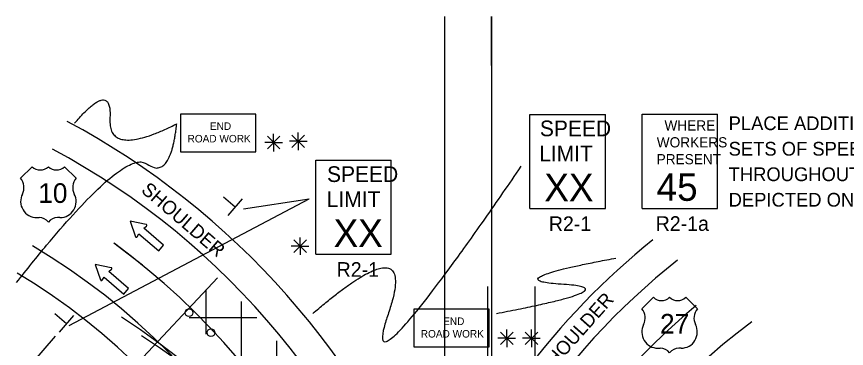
# Model space of a CAD drawing. Extents: x 16284 to 18465, y 5417 to 6974.
# Drawn here: x 16726.3 to 17149.1, y 6805 to 6974.1 of the extents above; entities that cross this region are included whole.
import ezdxf

# ---------------------------------------------------------------- set-up
doc = ezdxf.new("R2010")
doc.units = 0
for name, color, linetype in [('ALI_LEGAL_EX', 7, 'Continuous'), ('Level 3', 7, 'Continuous'), ('MT_SCRATCH_LEVEL_A', 7, 'Continuous'), ('MT_SCRATCH_LEVEL_E', 7, 'Continuous'), ('PAVT_EDGE_EX', 7, 'Continuous'), ('TRAFFIC_SIGNS_PR', 7, 'Continuous'), ('TYPICAL_EX', 7, 'Continuous'), ('TYPICAL_TEXT_DIMEN_PR', 7, 'Continuous')]:
    doc.layers.add(name, color=color, linetype=linetype)

msp = doc.modelspace()

# ---------------------------------------------------------------- linework, layer by layer
at = {"layer": 'ALI_LEGAL_EX'}
for p, q in [((16944.3, 6974.12), (16944.3, 6155.98)), ((16968.3, 6974.12), (16968.3, 6155.98)), ((16966.29, 6836.53), (16966.29, 5997.6)), ((16990.29, 6836.53), (16990.29, 5997.6))]:
    msp.add_line(p, q, dxfattribs=at)
for points in [[(16968.3, 6949.12), (16968.3, 6974.12)], [(16790.41, 6847.41), (16775.85, 6858.63)]]:
    msp.add_lwpolyline(points, dxfattribs=at)
for centre, radius, start, end in [((16561.13, 6564.7), 364, 0, 53.7921), ((17289.13, 6564.7), 340, 129.5666, 180), ((16583.12, 6514.52), 364, 0, 57.2958), ((16593.27, 6505.1), 364, 0, 57.2958)]:
    msp.add_arc(centre, radius, start, end, dxfattribs=at)
at = {"layer": 'Level 3'}
msp.add_line((16753.12, 6816.56), (16875.44, 6881.26), dxfattribs=at)
at = {"layer": 'MT_SCRATCH_LEVEL_A'}
for p, q in [((16822.96, 6812.16), (16822.96, 6834.85)), ((16840.96, 6792.95), (16840.96, 6828.84)), ((16814.28, 6820.72), (16848.67, 6820.72)), ((16858.96, 6769.95), (16858.96, 6808.85))]:
    msp.add_line(p, q, dxfattribs=at)
at = {"layer": 'MT_SCRATCH_LEVEL_E'}
for p, q in [((16792.3, 6868.17), (16784.11, 6869.75)), ((16784.11, 6869.75), (16786.92, 6861.91)), ((16791.11, 6866.22), (16792.51, 6867.36)), ((16801.16, 6857.58), (16791.11, 6866.22)), ((16787.75, 6861.83), (16788.67, 6863.38)), ((16788.67, 6863.38), (16798.72, 6854.74)), ((16798.72, 6854.74), (16801.16, 6857.58)), ((16774.54, 6846.12), (16766.34, 6847.69)), ((16766.34, 6847.69), (16769.15, 6839.86)), ((16773.34, 6844.17), (16774.74, 6845.31)), ((16783.4, 6835.52), (16773.34, 6844.17)), ((16769.98, 6839.78), (16770.91, 6841.33)), ((16770.91, 6841.33), (16780.96, 6832.68)), ((16780.96, 6832.68), (16783.4, 6835.52))]:
    msp.add_line(p, q, dxfattribs=at)
for centre, start, end in [((16792.21, 6867.72), 309.3361, 79.073), ((16787.35, 6862.07), 199.7248, 329.2637), ((16774.44, 6845.66), 309.3361, 79.073), ((16769.59, 6840.02), 199.7248, 329.2637)]:
    msp.add_arc(centre, 0.463, start, end, dxfattribs=at)
at = {"layer": 'PAVT_EDGE_EX'}
for centre, radius, start, end in [((16561.13, 6564.7), 404, 21.0961, 61.7914), ((16561.13, 6564.7), 388, 17.512, 61.7914), ((16561.13, 6564.7), 340, 0, 59.3712), ((17289.13, 6564.7), 380, 128.9165, 157.5011), ((17289.13, 6564.7), 364, 128.3887, 165.0045), ((16561.13, 6564.7), 324, 0, 59.2832), ((17289.13, 6564.7), 316, 126.5777, 180)]:
    msp.add_arc(centre, radius, start, end, dxfattribs=at)
at = {"layer": 'TRAFFIC_SIGNS_PR'}
for p, q in [((16987.86, 6924.25), (17026.26, 6924.25)), ((16987.86, 6876.25), (16987.86, 6924.25)), ((17026.26, 6876.25), (17026.26, 6924.25)), ((17045.06, 6924.34), (17083.46, 6924.34)), ((17045.06, 6876.34), (17045.06, 6924.34)), ((17083.46, 6876.34), (17083.46, 6924.34)), ((16878.7, 6900.93), (16917.1, 6900.93)), ((16878.7, 6852.93), (16878.7, 6900.93)), ((16917.1, 6852.93), (16917.1, 6900.93)), ((16987.86, 6876.25), (17026.26, 6876.25)), ((17045.06, 6876.34), (17083.46, 6876.34)), ((16878.7, 6852.93), (16917.1, 6852.93))]:
    msp.add_line(p, q, dxfattribs=at)
for points in [[(16809.82, 6905.22), (16848.22, 6905.22), (16848.22, 6924.42), (16809.82, 6924.42)], [(16928.61, 6805.76), (16967.01, 6805.76), (16967.01, 6824.96), (16928.61, 6824.96)]]:
    msp.add_lwpolyline(points, close=True, dxfattribs=at)
for centre in [(16814.15, 6823.16), (16825.34, 6812.99)]:
    msp.add_circle(centre, 2, dxfattribs=at)
at = {"layer": 'TYPICAL_EX'}
for p, q in [((16728.37, 6891.7), (16734.26, 6897.6)), ((16756.67, 6891.7), (16750.77, 6897.6)), ((16736.61, 6871.64), (16737.79, 6871.64)), ((16748.42, 6871.64), (16747.24, 6871.64)), ((17044.83, 6825.12), (17050.72, 6831.02)), ((17073.13, 6825.12), (17067.23, 6831.02)), ((17053.08, 6805.06), (17054.25, 6805.06)), ((17064.88, 6805.06), (17063.7, 6805.06))]:
    msp.add_line(p, q, dxfattribs=at)
for centre, radius, start, end in [((16738.39, 6901.89), 5.96, 226.1404, 313.8596), ((16746.64, 6901.89), 5.96, 226.1404, 313.8596), ((16722.78, 6886.98), 7.31, 333.0977, 40.1936), ((16762.25, 6886.98), 7.31, 139.8064, 206.9023), ((16736.63, 6879.89), 8.24, 152.6698, 269.9013), ((16748.41, 6879.89), 8.24, 270.0987, 27.3302), ((16737.81, 6865.74), 5.91, 37.1038, 90.1385), ((16747.23, 6865.74), 5.91, 89.8615, 142.8962), ((17054.85, 6835.31), 5.96, 226.1404, 313.8596), ((17063.11, 6835.31), 5.96, 226.1404, 313.8596), ((17039.24, 6820.4), 7.31, 333.0977, 40.1936), ((17078.72, 6820.4), 7.31, 139.8064, 206.9023), ((17053.09, 6813.31), 8.24, 152.6698, 269.9013), ((17064.87, 6813.31), 8.24, 270.0987, 27.3302), ((17054.27, 6799.16), 5.91, 37.1038, 90.1385), ((17063.69, 6799.16), 5.91, 89.8615, 142.8962)]:
    msp.add_arc(centre, radius, start, end, dxfattribs=at)
at = {"layer": 'TYPICAL_TEXT_DIMEN_PR'}
for p, q in [((16854.06, 6913.1), (16860.43, 6906.72)), ((16860.43, 6913.1), (16854.06, 6906.72)), ((16857.24, 6909.91), (16857.24, 6914.36)), ((16866.61, 6913.72), (16872.99, 6907.35)), ((16872.99, 6913.72), (16866.61, 6907.35)), ((16869.8, 6910.53), (16869.8, 6914.99)), ((16857.24, 6909.91), (16852.71, 6909.91)), ((16857.24, 6909.91), (16860.43, 6909.91)), ((16857.24, 6909.91), (16861.72, 6909.91)), ((16857.24, 6909.91), (16857.24, 6905.41)), ((16869.8, 6910.53), (16865.27, 6910.53)), ((16869.8, 6910.53), (16872.99, 6910.53)), ((16869.8, 6910.53), (16874.28, 6910.53)), ((16869.8, 6910.53), (16869.8, 6906.03)), ((16837.65, 6876.99), (16831.75, 6882.07)), ((16841.32, 6881.26), (16833.98, 6872.73)), ((16841.87, 6876.11), (16875.44, 6881.26)), ((16870.78, 6857.09), (16870.78, 6861.55)), ((16870.78, 6857.09), (16866.25, 6857.09)), ((16867.6, 6860.28), (16873.97, 6853.9)), ((16873.97, 6860.28), (16867.6, 6853.9)), ((16870.78, 6857.09), (16873.97, 6857.09)), ((16870.78, 6857.09), (16875.26, 6857.09)), ((16870.78, 6857.09), (16870.78, 6852.59)), ((16828.63, 6840.91), (16749.09, 6755.95)), ((16751.68, 6817.51), (16745.78, 6822.58)), ((16755.35, 6821.77), (16748.02, 6813.24)), ((16976.04, 6810.13), (16976.04, 6814.59)), ((16988.59, 6810.13), (16988.59, 6814.59)), ((16734.61, 6797.73), (16746.22, 6811.22)), ((16972.85, 6813.32), (16979.22, 6806.94)), ((16979.22, 6813.32), (16972.85, 6806.94)), ((16991.78, 6813.32), (16985.4, 6806.94)), ((16985.41, 6813.32), (16991.78, 6806.94)), ((16976.04, 6810.13), (16971.5, 6810.13)), ((16976.04, 6810.13), (16979.22, 6810.13)), ((16976.04, 6810.13), (16980.51, 6810.13)), ((16976.04, 6810.13), (16976.04, 6805.63)), ((16988.59, 6810.13), (16984.06, 6810.13)), ((16988.59, 6810.13), (16991.78, 6810.13)), ((16988.59, 6810.13), (16993.07, 6810.13)), ((16988.59, 6810.13), (16988.59, 6805.63))]:
    msp.add_line(p, q, dxfattribs=at)
for points in [[(16755.84, 6919.73), (16775.05, 6942.33), (16772.72, 6901.72), (16807.9, 6919.45)], [(16726.32, 6838.6), (16780.55, 6907.8), (16804.75, 6890.22), (16807.9, 6919.45)], [(16877.23, 6822.79), (16932.08, 6869.9), (16898.76, 6773.79), (16983.41, 6897.79)], [(16970.79, 6822.79), (17039.19, 6835.71), (16969.61, 6839.55), (17031.67, 6851.01)]]:
    msp.add_open_spline(points, degree=2, dxfattribs=at)

# ---------------------------------------------------------------- texts
at = {"layer": 'TRAFFIC_SIGNS_PR'}
for s, height, p in [('END', 3.831, (16824.82, 6916.35)), ('SPEED', 8, (16992.9, 6913.12)), ('WHERE', 5.2, (17056.37, 6916.03)), ('PLACE ADDITIONAL SUPPLEMENTAL', 7, (17089.06, 6916.24)), ('ROAD WORK', 3.831, (16813.43, 6909.97)), ('WORKERS', 5.2, (17052.44, 6907.43)), ('LIMIT', 8, (16992.56, 6900.32)), ('SETS OF SPEED LIMIT SIGNS', 7, (17089.06, 6903.24)), ('PRESENT', 5.2, (17052.37, 6898.83)), ('SPEED', 8, (16884.47, 6889.8)), ('THROUGHOUT THE WORK AREA AS', 7, (17089.06, 6890.24)), ('XX', 14.031, (16995.17, 6880.01)), ('45', 14.031, (17052.37, 6880.2)), ('LIMIT', 8, (16884.31, 6876.99)), ('DEPICTED ON TYPICAL M0100a.', 7, (17089.06, 6877.24)), ('XX', 14.031, (16887.82, 6856.69)), ('R2-1', 7.44, (16997.47, 6864.81)), ('R2-1a', 7.44, (17051.91, 6864.9)), ('R2-1', 7.44, (16889.38, 6841.49)), ('END', 3.831, (16943.62, 6816.89)), ('ROAD WORK', 3.831, (16932.22, 6810.5))]:
    msp.add_text(s, height=height, dxfattribs=at).set_placement(p)
at = {"layer": 'TYPICAL_EX'}
for s, p in [('10', (16737.36, 6879.13)), ('27', (17054.09, 6812.55))]:
    msp.add_text(s, height=10, dxfattribs=at).set_placement(p)
at = {"layer": 'TYPICAL_TEXT_DIMEN_PR'}
for rotation, p in [(319.2839, (16789.31, 6884.97)), (48.378, (16996.49, 6790.64))]:
    msp.add_text('SHOULDER', height=7, rotation=rotation, dxfattribs=at).set_placement(p)

doc.saveas('drawing.dxf')
